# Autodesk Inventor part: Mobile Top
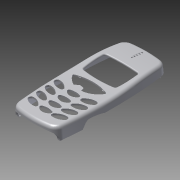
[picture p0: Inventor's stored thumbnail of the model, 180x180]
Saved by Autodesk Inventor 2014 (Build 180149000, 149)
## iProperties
Created: 2006-01
Part Number: Mobile Top
Document SubType Name: Modeling
Density: 1 g/cm^3
Material: Generic
Appearance: Default
Author: Autodesk
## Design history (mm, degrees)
sketch "Sketch1"
  geometry: L1 (-24, 54)-(24, 54); L2 (24, 54)-(24, -54); L3 (24, -54)-(-24, -54); L4 (-24, -54)-(-24, 54); A1 r 420.487 centre (396.487, -3.861) between (-20, 54) and (-21, -54); A2 r 420.487 centre (-396.487, -3.861) between (21, -54) and (20, 54); A3 r 90 centre (0, -33.75) between (20, 54) and (-20, 54); A4 r 80 centre (0, 23.195) between (-21, -54) and (21, -54); 1 further point
  constraints: 8 end point, 8 point on circle, 4 centre point, 4 point on line, 2 parallel, 2 tangent, 1 equal radius, 1 horizontal, 1 perpendicular
  dimensions: "d0" = 108 distance of L3.end L1.start; "d1" = 48 distance of L1.start L1.end; "d2" = 24 distance from line of point (0, 0) L4 (= 0.5 x d1); "d3" = 54 distance from line of point (0, 0) L1 (= 0.5 x d0); "d4" = 40 distance of A2.end A1.start; "d5" = 20 horizontal distance of point (0, 0) A1.start (= 0.5 x d4); "d6" = 42 distance of A2.start A1.end; "d7" = 90 radius of A3; "d8" = 80 radius of A4
extrude "Extrusion1" new body sketch "Sketch1" stored distance "d9" = 20; taper "d10" = 0 deg
fillet "Fillet2" dims "d70" = 8
sketch "Sketch7"
  geometry: L1 (-50.805, -3.5)-(-30.805, -3.5); L2 (-30.805, -3.5)-(-27.867, 0.545); L3 (-9.805, 0)-(56.25, 0); L4 (-56.805, -10)-(-56.805, 10) reference; L5 (56.25, -10)-(56.25, 10) reference; A1 r 8 centre (-58.802, -3.747) between (-50.805, -3.5) and (-56.805, 4); A2 r 5 centre (-23.821, -2.394) between (-23.915, 2.605) and (-27.867, 0.545); A3 r 48 centre (-23.015, -45.386) between (-10.546, 0.966) and (-23.915, 2.605); A4 r 1 centre (-10.805, 0) between (-9.805, 0) and (-10.546, 0.966)
  constraints: 8 point on circle, 6 end point, 4 centre point, 3 tangent, 1 horizontal, 1 horizontal alignment, 1 midpoint, 1 parallel, 1 point on line
  dimensions: "d51" = 20 distance of L1.start L1.end; "d52" = 8 radius of A1; "d53" = 6 distance from line of L4 L1.start; "d54" = 54 deg angle of L1 L2; "d55" = 5 distance of L1.end L2.end; "d56" = 3.5 distance between parallel lines of L1 L3; "d58" = 5 radius of A2; "d59" = 48 radius of A3; "d60" = 1 radius of A4; "d61" = 21 horizontal distance of L3.start L1.end; "d62" = 6 distance of L4.end A1.end; "d68" = 10 distance from line of L5.end L3
extrude_surface "ExtrusionSrf3" sketch "Sketch7" dims "d66" = 60, "d67" = 0
split "Split2"
fillet "Fillet1" dims "d69" = 0.5
sketch "Sketch12"
  geometry: L1 (-56.981, 8)-(-10.981, 8); L2 (-27.601, 0.545)-(-30.241, -3.088) reference; L3 (-31.05, -3.5)-(-49.773, -3.5) reference; L4 (-56.54, 2)-(-55.981, 10) reference; L5 (-55.981, 10)-(55.329, 10) reference; L6 (55.329, 10)-(56.028, 0) reference; L7 (56.028, 0)-(-8.808, 0) reference; A1 r 341.401 centre (-10.981, 349.401) between (-10.981, 8) and (19.482, 9.362); A2 r 160 centre (33.758, -150) between (56.329, 8.4) and (19.482, 9.362); A3 r 1 centre (-8.808, 1) between (-9.674, 0.5) and (-8.808, 0) reference; A4 r 1 centre (-10.54, 0) between (-9.674, 0.5) and (-10.281, 0.966) reference; A5 r 48 centre (-22.75, -45.386) between (-10.281, 0.966) and (-23.65, 2.605) reference; A6 r 5 centre (-23.556, -2.394) between (-23.65, 2.605) and (-27.601, 0.545) reference; A7 r 1 centre (-31.05, -2.5) between (-31.05, -3.5) and (-30.241, -3.088) reference; A8 r 1 centre (-49.773, -2.5) between (-50.725, -2.806) and (-49.773, -3.5) reference; A9 r 7 centre (-57.389, -4.948) between (-50.725, -2.806) and (-56.54, 2) reference
  constraints: 18 point on circle, 14 end point, 9 centre point, 4 horizontal, 3 tangent, 30 other
  dimensions: "d99" = 45 horizontal distance of L1.end L4.end; "d100" = 2 distance between parallel lines of L1 L5; "d101" = 1.6 vertical distance of L5.end A2.start; "d102" = 1 horizontal distance of L5.end A2.start; "d103" = 160 radius of A2; "d104" = 1 horizontal distance of L4.end L1.start
extrude_surface "ExtrusionSrf4" sketch "Sketch12" dims "d105" = 60, "d106" = 0
split "Split4"
fillet "Fillet7" dims "d108" = 3
feature "FaceDraft4" dims angle "d112" = 4 deg
shell "Shell3" dims "d113" = 1.5
sketch "Sketch13"
  geometry: L1 (-10.377, 0.699)-(-10.5, 0); L2 (-10.5, 0)-(10.5, 0); L3 (10.5, 0)-(10.377, 0.699); L4 (-14.135, 0)-(14.135, 0) reference; A1 r 40 centre (0, -36.707) between (8.85, 2.302) and (-8.85, 2.302); A2 r 2 centre (8.407, 0.352) between (10.377, 0.699) and (8.85, 2.302); A3 r 2 centre (-8.407, 0.352) between (-8.85, 2.302) and (-10.377, 0.699); 1 further point
  constraints: 6 end point, 6 point on circle, 4 tangent, 3 centre point, 1 collinear, 1 equal length, 1 equal radius, 1 horizontal
  dimensions: "d116" = 80 deg angle of L2 L1; "d118" = 40 radius of A1; "d569" = 2 radius of A2; "d570" = 0.6988 vertical distance of L1.start L1.end; "d571" = 21 distance of L2.end L1.end; "d572" = 10.5 distance of point (0, 0) L2.end (derived); "d573" = 0.6988 vertical distance of L2.end L3.end (derived)
extrude "Extrusion3" cut sketch "Sketch13" distance "d119" = 800; taper "d120" = 0 deg
sketch "Sketch14"
  geometry: A1 r 160 centre (0, -128.091) between (16.5, 31.056) and (-16.5, 31.056); A2 r 100 centre (0, 107.767) between (-16, 9.056) and (16, 9.056); A3 r 90 centre (73.052, 22.085) between (-16.5, 31.056) and (-16, 9.056); A4 r 90 centre (-73.052, 22.085) between (16, 9.056) and (16.5, 31.056); 3 further points
  constraints: 8 point on circle, 4 centre point, 2 horizontal alignment, 1 equal radius, 1 other
  dimensions: "d122" = 33 distance of A1.start A1.end; "d123" = 16.5 horizontal distance of point (0, 0) A1.end (derived); "d124" = 32 distance of A2.end A2.start; "d125" = 16 horizontal distance of point (0, 0) A2.start (derived); "d126" = 22 vertical distance of A2.start A1.end; "d127" = 160 radius of A1; "d128" = 100 radius of A2; "d129" = 90 radius of A3; "d130" = 25 vertical distance of A1.start point (10.5, 56.056)
extrude "Extrusion4" cut sketch "Sketch14" distance "d131" = 60; taper "d132" = 0 deg
fillet "Fillet9" dims "d133" = 2
fillet "Fillet10" dims "d134" = 1
sketch "Sketch15" dims "d138" = 22, "d139" = 20
  geometry: L1 (1, -9.972)-(0, -5.972); L2 (0, -5.972)-(-4.5, -5.172); L3 (-4.5, -5.172)-(-8, -8.163); A1 r 45 centre (0, -42) between (16.648, -0.193) and (-16.648, -0.193); 8 further points; 1 other entity
  constraints: 6 end point, 2 horizontal alignment, 2 point on circle, 2 vertical alignment, 1 centre point, 8 other
  dimensions: "d137" = 12 distance of point (0, 0) point (0, 12); "d140" = 45 radius of A1; "d141" = 42 distance of point (0, 0) A1.centre; "d164" = 1 horizontal distance of point (0, 0) L1.start; "d165" = 8 horizontal distance of point (0, 0) L3.end; "d166" = 4 vertical distance of L1.start L1.end; "d167" = 4.5 horizontal distance of L1.end L2.end; "d168" = 0.8 vertical distance of L1.end L2.end
extrude "Extrusion7" cut sketch "Sketch15" stored distance "d169" = 1.5; taper "d170" = 0 deg
fillet "Fillet12" dims "d171" = 1.2
workplane "Work Plane7"
sketch "Sketch17"
  geometry: L1 (-15.808, -1.477)-(15.808, -1.477); A1 r 18.61 centre (0.054, 8.614) between (-8, -8.163) and (1, -9.972)
  constraints: 2 end point, 2 point on circle, 1 centre point, 1 horizontal, 3 other
extrude "Extrusion8" cut sketch "Sketch17" distance "d173" = 2.5; taper "d174" = 0 deg
workplane "Work Plane8"
sketch "Sketch18" dims "d176" = 1
  geometry: A1 r 18.31 centre (-0.007, -19.291) between (1, -1.008) and (-8, -2.818); A2 r 19.31 centre (-0.007, -19.291) between (1.055, -0.01) and (-8.435, -1.917); 8 further points
  constraints: 4 point on circle, 2 centre point, 2 concentric, 2 horizontal alignment, 19 other
extrude "Extrusion9" cut sketch "Sketch18" distance "d177" = 0.5; taper "d178" = 0 deg
sketch "Sketch19"
  geometry: L1 (-1, 1.008)-(-0.189, 4.254) reference; L2 (-12.654, 12.165)-(-12.384, 11.797); L3 (-12.384, 11.797)-(-10.52, 12.182); L4 (-10.52, 12.182)-(-10.373, 12.769); A1 r 45 centre (0, -31.019) between (15.233, 11.324) and (-15.233, 11.324) reference
  constraints: 6 end point, 2 point on circle, 1 parallel
extrude "Extrusion10" join sketch "Sketch19" distance "d179" = 0.5; taper "d180" = 0 deg
mirror "Mirror1"
sketch "Sketch20"
  geometry: L1 (0, 0)-(41.879, 0) reference; A1 r 2.5 centre (3, -3) between (3.096, -0.502) and (1.347, -4.876); A2 r 12 centre (2.633, -12.493) between (11.888, -4.854) and (3.096, -0.502); A3 r 12 centre (9.281, 4.127) between (1.347, -4.876) and (10.715, -7.787); A4 r 1.8 centre (10.5, -6) between (10.715, -7.787) and (11.888, -4.854); A5 r 14 centre (20.939, -16.649) between (25.738, -3.497) and (16.141, -3.497); A6 r 1.6 centre (16.689, -5) between (16.141, -3.497) and (15.43, -5.987); A7 r 7 centre (20.939, -1.669) between (15.43, -5.987) and (26.449, -5.987); A8 r 1.6 centre (25.189, -5) between (26.449, -5.987) and (25.738, -3.497); A9 r 1.8 centre (10.818, -15) between (11.033, -16.787) and (12.206, -13.854); A10 r 12 centre (9.599, -4.873) between (1.665, -13.876) and (11.033, -16.787); A11 r 2.5 centre (3.318, -12) between (3.414, -9.502) and (1.665, -13.876); A12 r 12 centre (2.951, -21.493) between (12.206, -13.854) and (3.414, -9.502); A13 r 2.5 centre (3.831, -21) between (3.928, -18.502) and (2.178, -22.876); A14 r 12 centre (3.465, -30.493) between (12.719, -22.854) and (3.928, -18.502); A15 r 12 centre (10.113, -13.873) between (2.178, -22.876) and (11.546, -25.787); A16 r 1.8 centre (11.331, -24) between (11.546, -25.787) and (12.719, -22.854); A17 r 12 centre (37.198, -39.499) between (37.373, -27.5) and (27.95, -31.853); A18 r 2.5 centre (37.337, -30) between (39.008, -31.859) and (37.373, -27.5); A19 r 12 centre (30.987, -22.934) between (29.046, -34.776) and (39.008, -31.859); A20 r 1.8 centre (29.337, -33) between (27.95, -31.853) and (29.046, -34.776); A21 r 2.5 centre (4.542, -30) between (4.638, -27.502) and (2.889, -31.876); A22 r 12 centre (10.823, -22.873) between (2.889, -31.876) and (12.257, -34.787); A23 r 1.8 centre (12.042, -33) between (12.257, -34.787) and (13.43, -31.854); A24 r 12 centre (4.175, -39.493) between (13.43, -31.854) and (4.638, -27.502); A25 r 414.55 centre (417.426, 7.12) between (3, -3) and (4.542, -30); A26 r 417.487 centre (417.426, 7.12) between (0, 0) and (2.281, -37.041) reference; A27 r 7 centre (20.939, -28.669) between (15.43, -32.987) and (26.449, -32.987); A28 r 1.6 centre (25.189, -32) between (26.449, -32.987) and (25.738, -30.497); A29 r 14 centre (20.939, -43.649) between (25.738, -30.497) and (16.141, -30.497); A30 r 1.6 centre (16.689, -32) between (16.141, -30.497) and (15.43, -32.987); A31 r 1.6 centre (16.689, -14) between (16.141, -12.497) and (15.43, -14.987); A32 r 1.6 centre (25.189, -14) between (26.449, -14.987) and (25.738, -12.497); A33 r 7 centre (20.939, -10.669) between (15.43, -14.987) and (26.449, -14.987); A34 r 14 centre (20.939, -25.649) between (25.738, -12.497) and (16.141, -12.497); A35 r 1.6 centre (16.689, -23) between (16.141, -21.497) and (15.43, -23.987); A36 r 1.6 centre (25.189, -23) between (26.449, -23.987) and (25.738, -21.497); A37 r 7 centre (20.939, -19.669) between (15.43, -23.987) and (26.449, -23.987); A38 r 14 centre (20.939, -34.649) between (25.738, -21.497) and (16.141, -21.497); A39 r 1.8 centre (30.047, -24) between (28.66, -22.853) and (29.756, -25.776); A40 r 12 centre (37.909, -30.499) between (38.084, -18.5) and (28.66, -22.853); A41 r 12 centre (31.697, -13.934) between (29.756, -25.776) and (39.718, -22.859); A42 r 2.5 centre (38.047, -21) between (39.718, -22.859) and (38.084, -18.5); A43 r 1.8 centre (30.561, -15) between (29.174, -13.853) and (30.27, -16.776); A44 r 12 centre (32.211, -4.934) between (30.27, -16.776) and (40.232, -13.859); A45 r 12 centre (38.422, -21.499) between (38.597, -9.5) and (29.174, -13.853); A46 r 2.5 centre (38.561, -12) between (40.232, -13.859) and (38.597, -9.5); A47 r 1.8 centre (30.879, -6) between (29.491, -4.853) and (30.587, -7.776); A48 r 12 centre (32.528, 4.066) between (30.587, -7.776) and (40.55, -4.859); A49 r 12 centre (38.74, -12.499) between (38.915, -0.5) and (29.491, -4.853); A50 r 2.5 centre (38.879, -3) between (40.55, -4.859) and (38.915, -0.5); A51 r 414.55 centre (-375.547, 7.12) between (37.337, -30) and (38.879, -3); A52 r 417.487 centre (-375.547, 7.12) between (39.597, -37.041) and (41.879, 0) reference; 1 further point
  constraints: 104 point on circle, 50 centre point, 48 tangent, 9 vertical alignment, 7 horizontal alignment, 4 equal radius, 2 coincident, 2 concentric
  dimensions: "d181" = 12 radius of A2; "d182" = 12 radius of A3 (derived); "d183" = 2.5 radius of A1; "d184" = 1.8 radius of A4; "d185" = 7.5 horizontal distance of A4.centre A1.centre; "d186" = 3 vertical distance of A4.centre A1.centre; "d187" = 8.5 distance of A8.centre A6.centre; "d188" = 1.6 radius of A6; "d189" = 14 radius of A5; "d190" = 7 radius of A7; "d193" = 12 radius of A12; "d194" = 12 radius of A10 (derived); "d195" = 2.5 radius of A11; "d196" = 1.8 radius of A9; "d197" = 7.5 horizontal distance of A9.centre A11.centre (derived); "d198" = 3 vertical distance of A9.centre A11.centre (derived); "d199" = 12 radius of A14; "d200" = 12 radius of A15 (derived); "d201" = 2.5 radius of A13; "d202" = 1.8 radius of A16; "d203" = 7.5 horizontal distance of A16.centre A13.centre (derived); "d204" = 3 vertical distance of A16.centre A13.centre (derived); "d205" = 8 horizontal distance of A18.centre A20.centre; "d206" = 3 vertical distance of A18.centre A20.centre; "d207" = 1.8 radius of A20; "d208" = 12 radius of A17; "d209" = 12 radius of A19; "d210" = 2.5 radius of A18; "d211" = 12 radius of A24; "d212" = 12 radius of A22 (derived); "d213" = 2.5 radius of A21; "d214" = 1.8 radius of A23; "d215" = 7.5 horizontal distance of A23.centre A21.centre (derived); "d216" = 3 vertical distance of A23.centre A21.centre (derived); "d217" = 3 distance from line of L1 A1.centre; "d218" = 9 vertical distance of A9.centre A4.centre; "d219" = 9 vertical distance of A16.centre A9.centre; "d220" = 9 vertical distance of A23.centre A16.centre; "d222" = 3 horizontal distance of L1.start A1.centre; "d223" = 8.5 distance of A28.centre A30.centre (derived); "d224" = 1.6 radius of A30 (derived); "d225" = 14 radius of A29 (derived); "d226" = 7 radius of A27 (derived); "d227" = 8.5 distance of A32.centre A31.centre (derived); "d228" = 1.6 radius of A31 (derived); "d229" = 14 radius of A34 (derived); "d230" = 7 radius of A33 (derived); "d231" = 8.5 distance of A36.centre A35.centre (derived); "d232" = 1.6 radius of A35 (derived); "d233" = 14 radius of A38 (derived); "d234" = 7 radius of A37 (derived); "d235" = 9 distance of A32.centre A8.centre; "d236" = 9 distance of A36.centre A32.centre (derived); "d237" = 9 distance of A28.centre A36.centre (derived); "d238" = 5 distance from line of L1 A6.centre; "d239" = 8 horizontal distance of A42.centre A39.centre; "d240" = 3 vertical distance of A42.centre A39.centre; "d241" = 1.8 radius of A39; "d242" = 12 radius of A40; "d243" = 12 radius of A41; "d244" = 2.5 radius of A42; "d245" = 8 horizontal distance of A46.centre A43.centre; "d246" = 3 vertical distance of A46.centre A43.centre; "d247" = 1.8 radius of A43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
extrude "Extrusion12" cut sketch "Sketch20" stored distance "d259" = 10; taper "d260" = 0 deg
sketch "Sketch21"
  geometry: L1 (52.823, 8.86)-(53.02, 11.352); L2 (53.02, 11.352)-(40.06, 12.376); L3 (40.06, 12.376)-(39.863, 9.883); L4 (-68.28, 0)-(91.232, 0) reference; A1 r 158.5 centre (33.758, -150) between (53.437, 7.274) and (32.867, 8.497) reference; A2 r 160 centre (33.758, -150) between (53.623, 8.762) and (33.868, 10) reference; A3 r 90 centre (53.409, 98.858) between (39.863, 9.883) and (52.823, 8.86)
  constraints: 8 point on circle, 6 end point, 3 centre point, 2 perpendicular, 1 parallel, 8 other
  dimensions: "d261" = 90 radius of A3; "d262" = 13 distance of L1.end L2.end; "d264" = 2.5 distance of L1.start L1.end; "d266" = 0.8 horizontal distance of A2.start L1.start
revolve "Revolution1" sketch "Sketch21" stored, may be unused: angle "d265" = 90 deg
sketch "Sketch22"
  geometry: L1 (39.983, 8.378)-(51.947, 7.453); L2 (39.983, 8.378)-(39.998, 8.577); L3 (39.998, 8.577)-(51.945, 7.654); L4 (51.945, 7.654)-(51.947, 7.453); A1 r 158.5 centre (33.758, -150) between (53.437, 7.274) and (31.867, 8.489) reference
  constraints: 8 end point, 4 point on circle, 1 centre point, 1 parallel, 1 perpendicular, 4 other
  dimensions: "d267" = 12 distance of L1.start L1.end; "d268" = 1.5 distance of L1.end A1.start; "d575" = 0.2 distance between parallel lines of L1 L3; "d576" = 95 deg angle of L3 L4
extrude "Extrusion13" cut sketch "Sketch22" stored distance "d270" = 10; taper "d271" = 0 deg
sketch "Sketch23"
  geometry: L1 (10, 0)-(0, 0) reference; L2 (10, -11.983)-(0, -11.983) reference; L3 (-4, 0)-(14, 0); L4 (14, 0)-(12, -11.983); L5 (12, -11.983)-(-2, -11.983); L6 (-2, -11.983)-(-4, 0); 1 further point
  constraints: 8 end point, 2 point on line, 1 equal length, 1 parallel
  dimensions: "d272" = 18 distance of L3.start L3.end; "d273" = 9 horizontal distance of point (5, -51.201) L3.start (derived); "d274" = 14 distance of L4.end L5.end; "d275" = 7 horizontal distance of point (5, -51.201) L5.end (derived)
extrude "Extrusion14" cut sketch "Sketch23" stored distance "d276" = 10; taper "d277" = 0 deg
delete_face "Delete Face1"
fillet "Fillet13" dims "d278" = 2
sketch "Sketch24" dims "d280" = 1, "d281" = 0.5, "d285" = 1, "d286" = 0.5, "d287" = 1, "d288" = 0.5, "d289" = 1, "d290" = 0.5, "d291" = 1, "d292" = 0.5
  geometry: L1 (0, -68.275)-(0, 91.177) reference; L2 (6.639, 51.93)-(-6.639, 51.93) reference; 7 further points; 5 other entities
  constraints: 5 vertical alignment, 1 point on line, 10 other
  dimensions: "d293" = 2.5 distance of point (0, 48.647) point (0, 51.147); "d294" = 2.5 distance of point (0, 46.147) point (0, 48.647) (derived); "d295" = 2.5 distance of point (0, 46.147) point (0, 43.647) (derived); "d296" = 2.5 distance of point (0, 43.647) point (0, 41.147) (derived); "d552" = 0.8 distance from line of L2 point (0, 51.147)
extrude "Extrusion44" cut sketch "Sketch24" stored distance "d553" = 10; taper "d554" = 0 deg
sketch "Sketch26" dims "d301" = 0.8, "d302" = 0.8
  geometry: L1 (47.842, -0.062)-(47.842, 0.011); L2 (0.8, 0.011)-(0.796, 0.318); L3 (0.796, 0.318)-(0.794, -1.154); L4 (47.842, -0.062)-(47.842, -1.154); L5 (13.53, 64.607)-(14.113, 64.674); L6 (14.113, 64.674)-(14.113, 65.481); L7 (14.113, 65.481)-(13.821, 65.447); L8 (35.12, 64.606)-(32.991, 64.859); L9 (32.991, 64.859)-(32.991, 65.659); L10 (32.991, 65.659)-(34.821, 65.447); L11 (1.588, -1.154)-(0.085, -1.154) reference; L12 (48.557, -1.154)-(47.053, -1.154) reference; 16 further points
  constraints: 20 end point, 2 parallel, 2 point on line, 1 collinear, 1 vertical, 38 other
  dimensions: "d303" = 0.8 distance of L8.end L9.end
extrude "Extrusion17" cut sketch "Sketch26" distance "d304" = 0.6; taper "d305" = 0 deg
fillet "Fillet15" dims "d306" = 1
sketch "Sketch25"
  geometry: L1 (5.22, 59.588)-(11.22, 59.588); L2 (11.22, 59.588)-(11.22, 63.588); L3 (43.421, 59.588)-(37.421, 59.588); L4 (37.421, 59.588)-(37.421, 63.588); 6 further points
  constraints: 8 end point, 3 perpendicular, 2 equal length, 1 horizontal, 8 other
  dimensions: "d297" = 6 distance of L1.start L1.end; "d298" = 4 distance of L1.end L2.end
extrude "Extrusion16" join sketch "Sketch25" stored distance "d299" = 6; taper "d300" = 0 deg
sketch "Sketch27" dims "d307" = 0.5, "d308" = 0.5
  geometry: L1 (5.22, 59.588)-(5.672, 59.373); L2 (11.251, 63.087)-(11.22, 63.588); L3 (37.421, 63.588)-(37.399, 63.085); L4 (43.421, 59.588)-(42.97, 59.373); 4 further points
  constraints: 8 end point, 16 other
extrude "Extrusion18" cut sketch "Sketch27" distance "d309" = 3; taper "d310" = 0 deg
sketch "Sketch28"
  geometry: L1 (11.22, 63.082)-(11.22, 59.588) reference; L2 (11.22, 59.588)-(5.779, 59.588) reference; L3 (37.421, 59.588)-(37.421, 63.082) reference; L4 (42.863, 59.588)-(37.421, 59.588) reference; L5 (11.22, 61.588)-(6.779, 59.588); L6 (37.421, 61.588)-(41.863, 59.588)
  constraints: 4 end point, 4 point on line
  dimensions: "d311" = 2 distance from line of L2 L5.start; "d312" = 1 distance of L2.end L5.end; "d313" = 1 distance of L4.start L6.end (derived); "d314" = 2 distance from line of L4 L6.start (derived)
extrude "Extrusion19" cut sketch "Sketch28" distance "d315" = 3; taper "d316" = 0 deg
sketch "Sketch29"
  geometry: L1 (11.22, 63.082)-(11.22, 61.588) reference; L2 (6.779, 59.588)-(11.22, 61.588) reference; L3 (37.421, 61.588)-(37.421, 63.082) reference; L4 (37.421, 61.588)-(41.863, 59.588) reference; L5 (10.72, 63.006)-(10.72, 61.362); L6 (37.921, 63.006)-(37.921, 61.362); 2 further points
  constraints: 4 end point, 2 parallel, 2 point on line, 4 other
  dimensions: "d317" = 0.5 distance between parallel lines of L1 L5; "d318" = 0.5 distance between parallel lines of L3 L6 (derived)
extrude "Extrusion20" cut sketch "Sketch29" distance "d319" = 3; taper "d320" = 0 deg
fillet "Fillet16" dims "d321" = 1
fillet "Fillet17" dims "d322" = 0.1
fillet "Fillet18" dims "d323" = 0.1
sketch "Sketch30"
  geometry: L1 (5.767, 0)-(0, 0) reference; L2 (0, 0)-(0, -3) reference; L3 (0.6, -0.6)-(5.167, -0.6); L4 (5.167, -0.6)-(5.167, -2.4); L5 (5.167, -2.4)-(0.6, -2.4); L6 (0.6, -2.4)-(0.6, -0.6); L7 (2.4, -0.6)-(2.4, -2.4); L8 (3, -0.6)-(3, -2.4); L9 (-31.368, -0.6)-(-26.801, -0.6); L10 (-26.801, -0.6)-(-26.801, -2.4); L11 (-26.801, -2.4)-(-31.368, -2.4); L12 (-31.368, -2.4)-(-31.368, -0.6); L13 (-29.201, -0.6)-(-29.201, -2.4); L14 (-28.601, -0.6)-(-28.601, -2.4); L15 (-26.201, 0)-(-26.201, -3) reference; L16 (-26.201, 0)-(-31.968, 0) reference
  constraints: 24 end point, 8 point on line, 6 parallel, 4 perpendicular, 2 horizontal
  dimensions: "d324" = 0.6 distance between parallel lines of L15 L10 (derived); "d325" = 0.6 distance between parallel lines of L16 L9; "d326" = 0.6 distance from line of L15.end L11 (derived); "d327" = 0.6 distance from line of L16.end L12 (derived); "d328" = 0.6 distance between parallel lines of L14 L13 (derived); "d329" = 1.8 distance between parallel lines of L10 L14; "d330" = 0.6 distance between parallel lines of L1 L3 (derived); "d331" = 0.6 distance between parallel lines of L2 L6 (derived); "d332" = 0.6 distance from line of L1.start L4 (derived); "d333" = 0.6 distance from line of L2.end L5 (derived); "d334" = 0.6 distance between parallel lines of L8 L7 (derived); "d335" = 1.8 distance between parallel lines of L6 L7 (derived)
extrude "Extrusion21" cut sketch "Sketch30" distance "d336" = 2; taper "d337" = -2 deg
fillet "Fillet19" dims "d338" = 2
fillet "Fillet20" dims "d339" = 0.3
fillet "Fillet22" dims "d341" = 0.3
fillet "Fillet21" dims "d340" = 0.3
sketch "Sketch31" dims "d342" = 0.8, "d343" = 0.8 (derived), "d344" = 1, "d345" = 1
  geometry: L1 (43.35, 2.065)-(41.554, 2.197); L2 (2.055, 2.197)-(0.265, 2.006); L3 (43.023, 20.177)-(44.828, 20.177); L4 (44.828, 19.414)-(44.828, 20.177); L5 (43.023, 19.359)-(43.023, 20.177); L6 (-1.219, 20.871)-(0.587, 20.871); L7 (0.587, 19.341)-(0.587, 20.871); L8 (-1.219, 19.403)-(-1.219, 20.871); A1 r 419.585 centre (418.291, 46.474) between (-0.411, 19.274) and (1.061, 2.091) reference; A2 r 419.585 centre (-374.682, 46.474) between (42.549, 2.091) and (44.02, 19.274) reference; A3 r 420.385 centre (418.291, 46.474) between (-1.209, 19.222) and (0.265, 2.006); A4 r 420.385 centre (-374.682, 46.474) between (43.35, 2.065) and (44.818, 19.222); A5 r 418.585 centre (418.291, 46.474) between (0.587, 19.339) and (2.055, 2.197); A6 r 418.585 centre (-374.682, 46.474) between (41.554, 2.197) and (43.022, 19.339); 2 further points
  constraints: 16 end point, 8 point on circle, 5 perpendicular, 4 centre point, 4 concentric, 1 horizontal, 14 other
extrude "Extrusion22" cut sketch "Sketch31" distance "d346" = 0.8; taper "d347" = 0 deg
fillet "Fillet23" dims "d348" = 1
sketch "Sketch32"
  geometry: L1 (-40.934, 2.091)-(-41.73, 2.006) reference; L2 (1.356, 2.065)-(0.557, 2.123) reference; L3 (-40.934, 2.091)-(-38.934, 2.304); L4 (-38.934, 2.304)-(-38.934, -0.498); L5 (-41.768, -0.498)-(-40.103, -0.498) reference; L6 (-40.103, -0.498)-(-38.934, -0.498); L7 (-0.277, -0.498)-(1.388, -0.498) reference; L8 (0.557, 2.123)-(-1.443, 2.27); L9 (-1.443, 2.27)-(-1.443, -0.498); L10 (-0.277, -0.498)-(-1.443, -0.498); L11 (-41.73, 2.006)-(-40.936, -0.498); L12 (1.356, 2.065)-(0.555, -0.498)
  constraints: 16 end point, 4 collinear, 3 midpoint, 2 vertical, 1 point on line
  dimensions: "d349" = 2 horizontal distance of L3.end L1.start; "d350" = 2 horizontal distance of L2.end L8.end (derived)
extrude "Extrusion23" join sketch "Sketch32" stored distance "d351" = 4; taper "d352" = 0 deg
sketch "Sketch33"
  geometry: L1 (-38.934, -0.498)-(-40.936, -0.498) reference; L2 (-38.934, 2.304)-(-38.934, -0.498) reference; L3 (-41.73, 2.006)-(-38.934, 2.304) reference; L4 (-40.936, -0.498)-(-41.73, 2.006) reference; L5 (-1.443, 2.27)-(1.356, 2.065) reference; L6 (-1.443, -0.498)-(-1.443, 2.27) reference; L7 (0.555, -0.498)-(-1.443, -0.498) reference; L8 (1.356, 2.065)-(0.555, -0.498) reference
extrude "Extrusion24" cut sketch "Sketch33" distance "d353" = 1; taper "d354" = 0 deg
workplane "Work Plane13"
sketch "Sketch48"
  geometry: L1 (-3.205, -4.18)-(-6.006, -4.18) reference; L2 (-3.205, -4.18)-(-3.205, -7.18) reference; L3 (-3.433, -4.18)-(-3.205, -4.18); L4 (-3.205, -5.723)-(-3.205, -4.18); A1 r 8.5 centre (4.764, -6.426) between (-0.042, 0.584) and (-3.433, -4.18); A2 r 8 centre (4.764, -6.426) between (2.768, 1.32) and (-3.232, -6.18) reference; 2 further points
  constraints: 4 end point, 3 point on circle, 2 point on line, 1 centre point, 1 collinear, 1 concentric, 1 perpendicular, 6 other
  dimensions: "d379" = 0.5 radial gap between concentric circles of A1 A2
extrude "Extrusion34" join sketch "Sketch48" stored distance "d380" = 1.5; taper "d381" = 0 deg
sketch "Sketch50"
  geometry: L1 (-2.001, 3)-(-2.001, 1.456) reference; L2 (-5.793, 7.18)-(-5.793, -1.377); L3 (-5.793, -1.377)-(-2.001, -1.377); L4 (-2.001, -1.377)-(-2.001, 1.456); A1 r 6.8 centre (-8.48, 0.933) between (-2.001, 3) and (-5.793, 7.18)
  constraints: 6 end point, 2 perpendicular, 2 point on circle, 1 centre point, 1 parallel
  dimensions: "d395" = 6.8 radius of A1
extrude "Extrusion35" cut sketch "Sketch50" stored distance "d382" = 7; taper "d383" = 0 deg
sketch "Sketch53"
  geometry: L1 (3, -0.291)-(3, 0.229) reference
sketch "3D Sketch4"
feature "LoftSrf3" sketch "Sketch53", "3D Sketch4" dims "d384" = 0, "d385" = 90 deg, "d386" = 0, "d387" = 90 deg, "d388" = 0, "d389" = 90 deg
  node "Edges2"
feature "Extend1" dims "d390" = 0.25
thicken "Thicken1" dims "d391" = 1, "d392" = 1
workplane "Work Plane15"
sketch "Sketch54"
  geometry: L1 (3.433, -4.18)-(3.205, -4.18) reference; L2 (3.205, -5.723)-(3.205, -4.18) reference; A1 r 8.5 centre (-4.764, -6.426) between (3.433, -4.18) and (0.042, 0.584) reference; A2 r 8 centre (-4.764, -6.426) between (3.232, -6.18) and (-2.768, 1.32) reference; 1 further point
  constraints: 1 other
extrude "Extrusion36" join sketch "Sketch54" stored distance "d393" = 7; taper "d394" = 0 deg
sketch "Sketch55"
  geometry: L1 (1.998, 3)-(1.998, 1.456) reference; L2 (5.793, 7.18)-(5.793, -3.94); L3 (5.793, -3.94)-(1.998, -3.526); L4 (1.998, -3.526)-(1.998, 1.456); A1 r 6.8 centre (8.476, 0.931) between (5.793, 7.18) and (1.998, 3)
  constraints: 6 end point, 2 parallel, 2 point on circle, 1 centre point
  dimensions: "d396" = 6.8 radius of A1
extrude "Extrusion37" cut sketch "Sketch55" stored distance "d397" = 7; taper "d398" = 0 deg
sketch "3D Sketch5"
feature "LoftSrf4" sketch "3D Sketch5" dims "d399" = 0, "d400" = 90 deg, "d401" = 0, "d402" = 90 deg, "d403" = 0, "d404" = 90 deg
  node "Edges3"
  node "Edges4"
feature "Extend2" dims "d405" = 0.25
thicken "Thicken2" dims "d406" = 1, "d407" = 1
sketch "Sketch56"
  geometry: L1 (-50.335, -3.5)-(-50.335, -9.751); L2 (-50.335, -9.751)-(-55.259, -9.751); L3 (-55.259, -9.751)-(-55.076, -3.044); L4 (-55.076, -3.044)-(-50.833, -3.044)
  constraints: 8 end point, 1 parallel, 1 perpendicular, 1 vertical, 1 other
extrude "Extrusion38" cut sketch "Sketch56" stored distance "d408" = 7; taper "d409" = 0 deg
fillet "Fillet24" dims "d410" = 0.5
sketch "Sketch57"
  geometry: L1 (2.5, 2.521)-(2.5, 1.289); L2 (2.5, 1.289)-(0.5, 0.72); L3 (0.5, 0.72)-(0.5, 2.521); L4 (0.5, 2.521)-(2.5, 2.521); L5 (3, 2.854)-(3, 0.789) reference; L6 (0, 0.52)-(0, 2.895) reference; L7 (0, 3.021)-(3, 3.021) reference
  constraints: 8 end point, 1 parallel, 1 perpendicular, 1 vertical
  dimensions: "d411" = 0.5 distance between parallel lines of L5 L1; "d412" = 0.5 distance between parallel lines of L4 L7 (derived); "d413" = 0.5 distance between parallel lines of L6 L3 (derived); "d414" = 0.2 vertical distance of L6.start L2.end; "d415" = 0.5 horizontal distance of L5.end L1.end
extrude "Extrusion39" cut sketch "Sketch57" distance "d416" = 1.8; taper "d417" = -2 deg
fillet "Fillet25" dims "d418" = 0.1
sketch "Sketch58"
  geometry: L1 (-3, 2.537)-(-3, 0.789) reference; L2 (0, 3.037)-(-3, 3.037) reference; L3 (-3, 0.789)-(-2, 0.789) reference; L4 (0, 0.52)-(0, 2.537) reference; L5 (-2.5, 2.537)-(-2.5, 1.289); L6 (-2.5, 1.289)-(-0.5, 0.72); L7 (-0.5, 0.72)-(-0.5, 2.537); L8 (-0.5, 2.537)-(-2.5, 2.537)
  constraints: 8 end point, 2 parallel, 1 perpendicular
  dimensions: "d419" = 0.5 distance between parallel lines of L2 L8; "d420" = 0.5 distance between parallel lines of L1 L5 (derived); "d421" = 0.5 distance between parallel lines of L4 L7 (derived); "d422" = 0.5 horizontal distance of L1.end L5.end (derived); "d423" = 0.2 vertical distance of L4.start L6.end
extrude "Extrusion40" cut sketch "Sketch58" distance "d424" = 1.8; taper "d425" = -2 deg
fillet "Fillet26" dims "d426" = 0.1
fillet "Fillet27" dims "d427" = 0.1
fillet "Fillet28" dims "d428" = 0.1
fillet "Fillet29" dims "d429" = 0.1
fillet "Fillet30" dims "d430" = 0.1
workplane "Work Plane16"
sketch "Sketch59"
  geometry: L1 (0, -4.826)-(0, -0.108) reference; L2 (0, -0.108)-(2.9, -0.108) reference; L3 (0, 27.54)-(0, 32.258) reference; L4 (0, 27.54)-(2.9, 27.54) reference; L5 (0.5, -4.326)-(2.5, -4.326); L6 (2.5, -4.326)-(2.5, -0.608); L7 (2.5, -0.608)-(0.5, -0.608); L8 (0.5, -0.608)-(0.5, -4.326); L9 (0.5, 28.04)-(2.5, 28.04); L10 (2.5, 28.04)-(2.5, 31.758); L11 (2.5, 31.758)-(0.5, 31.758); L12 (0.5, 31.758)-(0.5, 28.04)
  constraints: 16 end point, 4 parallel, 2 horizontal, 2 perpendicular, 1 collinear
  dimensions: "d431" = 0.5 distance between parallel lines of L1 L8; "d432" = 0.5 distance between parallel lines of L7 L2 (derived); "d433" = 0.5 distance between parallel lines of L3 L12 (derived); "d434" = 0.5 distance between parallel lines of L4 L9 (derived); "d435" = 2 distance of L5.start L5.end; "d436" = 0.5 distance from line of L1.start L5 (derived); "d437" = 0.5 distance from line of L3.end L11 (derived)
extrude "Extrusion41" cut sketch "Sketch59" distance "d438" = 1.8; taper "d439" = 0 deg
fillet "Fillet31" dims "d440" = 1
workplane "Work Plane17"
sketch "Sketch62" dims "d460" = 1.5
  geometry: 20 further points
  constraints: 40 other
extrude "Extrusion43" cut sketch "Sketch62" stored distance "d461" = 0.4; taper "d462" = 0 deg
body "Solid1"
body "Srf1"
body "Srf2"
body "Srf3"
body "Srf4"
other parameters: "d175" = 0
